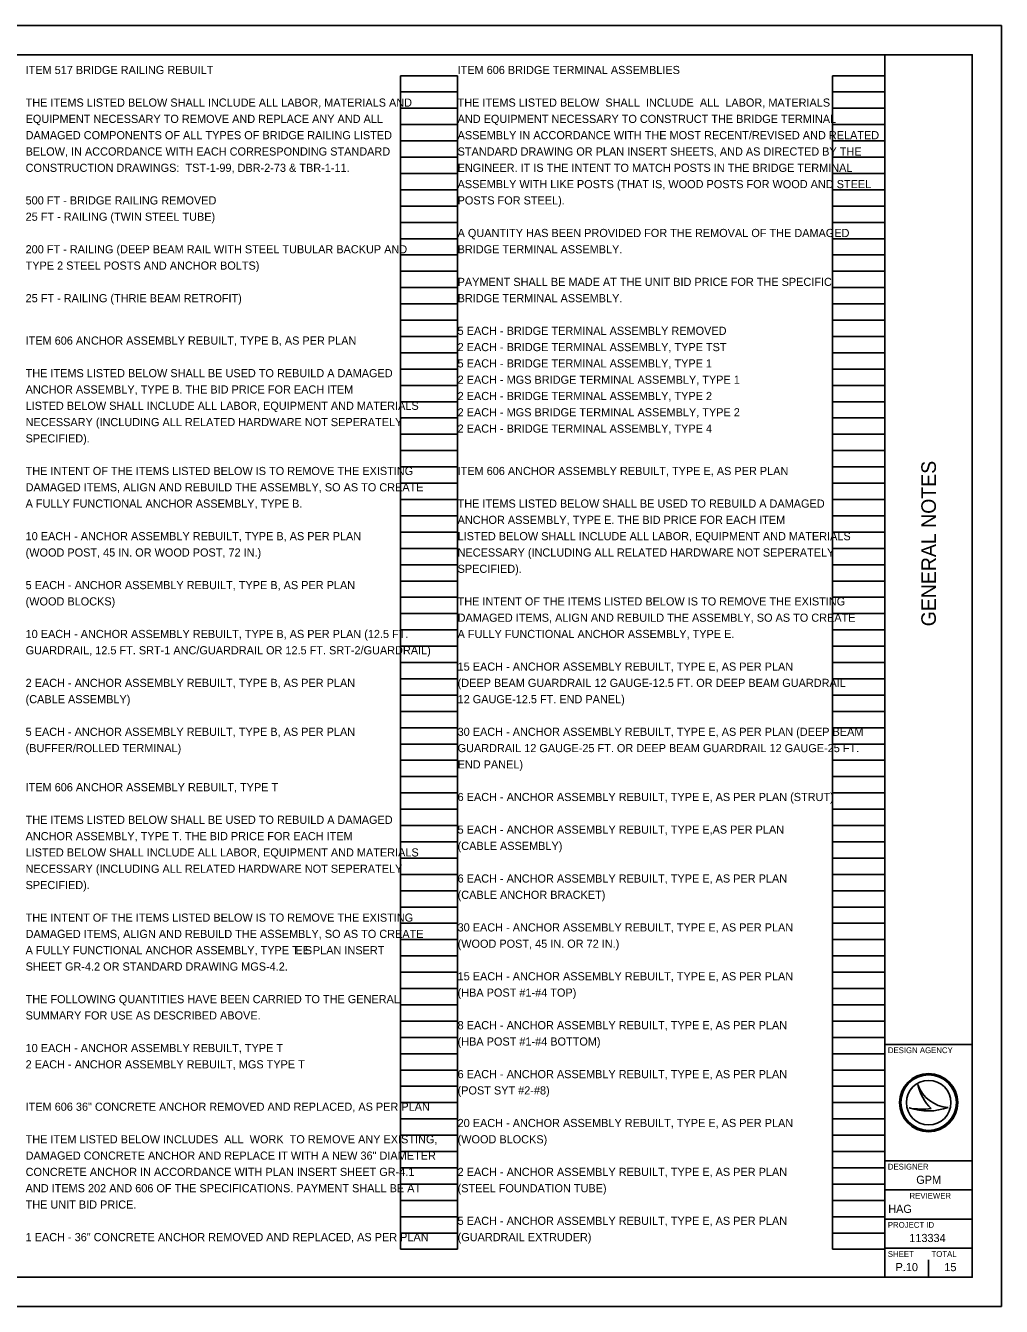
# Model space of a CAD drawing. Extents: x 0 to 34, y 0 to 22.
# Drawn here: x 17.24 to 34, y 0 to 22 of the extents above; entities that cross this region are included whole.
import ezdxf

# ---------------------------------------------------------------- set-up
doc = ezdxf.new("R2010")
doc.units = 0
for name, color, linetype in [('Default', 7, 'Continuous'), ('SH_Border', 7, 'Continuous'), ('SH_Cut_Line', 7, 'Continuous'), ('SH_Data', 7, 'Continuous')]:
    doc.layers.add(name, color=color, linetype=linetype)

msp = doc.modelspace()

# ---------------------------------------------------------------- linework, layer by layer
at = {"layer": 'SH_Border'}
for p, q in [((32, 0.5), (32, 21.5)), ((32, 4.5), (33.5, 4.5)), ((32, 2.5), (33.5, 2.5)), ((32, 2), (33.5, 2)), ((32, 1.5), (33.5, 1.5)), ((32, 1), (33.5, 1))]:
    msp.add_line(p, q, dxfattribs=at)
msp.add_lwpolyline([(1.5, 21.5), (33.5, 21.5), (33.5, 0.5), (1.5, 0.5)], close=True, dxfattribs=at)
at = {"layer": 'SH_Cut_Line'}
msp.add_lwpolyline([(0, 0), (34, 0), (34, 22), (0, 22)], close=True, dxfattribs=at)
at = {"layer": 'SH_Data'}
for p, q in [((23.68, 0.98), (23.68, 21.14)), ((23.68, 21.14), (24.66, 21.14)), ((24.66, 0.98), (24.66, 21.14)), ((31.1, 0.98), (31.1, 21.14)), ((31.1, 21.14), (32, 21.14)), ((32, 0.98), (32, 21.14)), ((23.68, 20.86), (24.66, 20.86)), ((31.1, 20.86), (32, 20.86)), ((23.68, 20.58), (24.66, 20.58)), ((31.1, 20.58), (32, 20.58)), ((23.68, 20.3), (24.66, 20.3)), ((31.1, 20.3), (32, 20.3)), ((23.68, 20.02), (24.66, 20.02)), ((31.1, 20.02), (32, 20.02)), ((23.68, 19.74), (24.66, 19.74)), ((31.1, 19.74), (32, 19.74)), ((23.68, 19.46), (24.66, 19.46)), ((31.1, 19.46), (32, 19.46)), ((23.68, 19.18), (24.66, 19.18)), ((31.1, 19.18), (32, 19.18)), ((23.68, 18.9), (24.66, 18.9)), ((31.1, 18.9), (32, 18.9)), ((23.68, 18.62), (24.66, 18.62)), ((31.1, 18.62), (32, 18.62)), ((23.68, 18.34), (24.66, 18.34)), ((31.1, 18.34), (32, 18.34)), ((23.68, 18.06), (24.66, 18.06)), ((31.1, 18.06), (32, 18.06)), ((23.68, 17.78), (24.66, 17.78)), ((31.1, 17.78), (32, 17.78)), ((23.68, 17.5), (24.66, 17.5)), ((31.1, 17.5), (32, 17.5)), ((23.68, 17.22), (24.66, 17.22)), ((31.1, 17.22), (32, 17.22)), ((23.68, 16.94), (24.66, 16.94)), ((31.1, 16.94), (32, 16.94)), ((23.68, 16.66), (24.66, 16.66)), ((31.1, 16.66), (32, 16.66)), ((23.68, 16.38), (24.66, 16.38)), ((31.1, 16.38), (32, 16.38)), ((23.68, 16.1), (24.66, 16.1)), ((31.1, 16.1), (32, 16.1)), ((23.68, 15.82), (24.66, 15.82)), ((31.1, 15.82), (32, 15.82)), ((23.68, 15.54), (24.66, 15.54)), ((31.1, 15.54), (32, 15.54)), ((23.68, 15.26), (24.66, 15.26)), ((31.1, 15.26), (32, 15.26)), ((23.68, 14.98), (24.66, 14.98)), ((31.1, 14.98), (32, 14.98)), ((23.68, 14.7), (24.66, 14.7)), ((31.1, 14.7), (32, 14.7)), ((23.68, 14.42), (24.66, 14.42)), ((31.1, 14.42), (32, 14.42)), ((23.68, 14.14), (24.66, 14.14)), ((31.1, 14.14), (32, 14.14)), ((23.68, 13.86), (24.66, 13.86)), ((31.1, 13.86), (32, 13.86)), ((23.68, 13.58), (24.66, 13.58)), ((31.1, 13.58), (32, 13.58)), ((23.68, 13.3), (24.66, 13.3)), ((31.1, 13.3), (32, 13.3)), ((23.68, 13.02), (24.66, 13.02)), ((31.1, 13.02), (32, 13.02)), ((23.68, 12.74), (24.66, 12.74)), ((31.1, 12.74), (32, 12.74)), ((23.68, 12.46), (24.66, 12.46)), ((31.1, 12.46), (32, 12.46)), ((23.68, 12.18), (24.66, 12.18)), ((31.1, 12.18), (32, 12.18)), ((23.68, 11.9), (24.66, 11.9)), ((31.1, 11.9), (32, 11.9)), ((23.68, 11.62), (24.66, 11.62)), ((31.1, 11.62), (32, 11.62)), ((23.68, 11.34), (24.66, 11.34)), ((31.1, 11.34), (32, 11.34)), ((23.68, 11.06), (24.66, 11.06)), ((31.1, 11.06), (32, 11.06)), ((23.68, 10.78), (24.66, 10.78)), ((31.1, 10.78), (32, 10.78)), ((23.68, 10.5), (24.66, 10.5)), ((31.1, 10.5), (32, 10.5)), ((23.68, 10.22), (24.66, 10.22)), ((31.1, 10.22), (32, 10.22)), ((23.68, 9.94), (24.66, 9.94)), ((31.1, 9.94), (32, 9.94)), ((23.68, 9.66), (24.66, 9.66)), ((31.1, 9.66), (32, 9.66)), ((23.68, 9.38), (24.66, 9.38)), ((31.1, 9.38), (32, 9.38)), ((23.68, 9.1), (24.66, 9.1)), ((31.1, 9.1), (32, 9.1)), ((23.68, 8.82), (24.66, 8.82)), ((31.1, 8.82), (32, 8.82)), ((23.68, 8.54), (24.66, 8.54)), ((31.1, 8.54), (32, 8.54)), ((23.68, 8.26), (24.66, 8.26)), ((31.1, 8.26), (32, 8.26)), ((23.68, 7.98), (24.66, 7.98)), ((31.1, 7.98), (32, 7.98)), ((23.68, 7.7), (24.66, 7.7)), ((31.1, 7.7), (32, 7.7)), ((23.68, 7.42), (24.66, 7.42)), ((31.1, 7.42), (32, 7.42)), ((23.68, 7.14), (24.66, 7.14)), ((31.1, 7.14), (32, 7.14)), ((23.68, 6.86), (24.66, 6.86)), ((31.1, 6.86), (32, 6.86)), ((23.68, 6.58), (24.66, 6.58)), ((31.1, 6.58), (32, 6.58)), ((23.68, 6.3), (24.66, 6.3)), ((31.1, 6.3), (32, 6.3)), ((23.68, 6.02), (24.66, 6.02)), ((31.1, 6.02), (32, 6.02)), ((23.68, 5.74), (24.66, 5.74)), ((31.1, 5.74), (32, 5.74)), ((23.68, 5.46), (24.66, 5.46)), ((31.1, 5.46), (32, 5.46)), ((23.68, 5.18), (24.66, 5.18)), ((31.1, 5.18), (32, 5.18)), ((23.68, 4.9), (24.66, 4.9)), ((31.1, 4.9), (32, 4.9)), ((23.68, 4.62), (24.66, 4.62)), ((31.1, 4.62), (32, 4.62)), ((23.68, 4.34), (24.66, 4.34)), ((31.1, 4.34), (32, 4.34)), ((23.68, 4.06), (24.66, 4.06)), ((31.1, 4.06), (32, 4.06)), ((23.68, 3.78), (24.66, 3.78)), ((31.1, 3.78), (32, 3.78)), ((32.567, 3.81), (32.567, 3.81)), ((23.68, 3.5), (24.66, 3.5)), ((31.1, 3.5), (32, 3.5)), ((32.417, 3.41), (32.417, 3.41)), ((32.75, 3.5), (32.75, 3.5)), ((33.087, 3.419), (33.087, 3.419)), ((23.68, 3.22), (24.66, 3.22)), ((31.1, 3.22), (32, 3.22)), ((23.68, 2.94), (24.66, 2.94)), ((31.1, 2.94), (32, 2.94)), ((23.68, 2.66), (24.66, 2.66)), ((31.1, 2.66), (32, 2.66)), ((23.68, 2.38), (24.66, 2.38)), ((31.1, 2.38), (32, 2.38)), ((23.68, 2.1), (24.66, 2.1)), ((31.1, 2.1), (32, 2.1)), ((23.68, 1.82), (24.66, 1.82)), ((31.1, 1.82), (32, 1.82)), ((23.68, 1.54), (24.66, 1.54)), ((31.1, 1.54), (32, 1.54)), ((23.68, 1.26), (24.66, 1.26)), ((31.1, 1.26), (32, 1.26)), ((23.68, 0.98), (24.66, 0.98)), ((31.1, 0.98), (32, 0.98)), ((32.375, 0.675), (32.375, 0.675)), ((32.75, 0.5), (32.75, 0.8))]:
    msp.add_line(p, q, dxfattribs=at)
for radius in [0.5, 0.477, 0.477, 0.382]:
    msp.add_circle((32.75, 3.5), radius, dxfattribs=at)
for centre, radius, start, end in [((33.116, 3.998), 0.58, 198.9257, 198.9319), ((33.347, 3.97), 0.796, 191.6379, 191.6421), ((33.116, 3.998), 0.58, 198.9319, 267.1657), ((33.347, 3.97), 0.796, 191.6421, 226.0947), ((32.739, 4.37), 1.013, 251.4576, 290.0832), ((32.648, 4.654), 1.266, 259.4964, 259.4995), ((32.739, 4.37), 1.013, 251.4527, 251.4576), ((32.648, 4.654), 1.266, 259.4995, 276.6672)]:
    msp.add_arc(centre, radius, start, end, dxfattribs=at)

# ---------------------------------------------------------------- texts
at = {"layer": 'Default'}
for s, p in [('ITEM 517 BRIDGE RAILING REBUILT', (17.24, 21.168)), ('ITEM 606 BRIDGE TERMINAL ASSEMBLIES', (24.66, 21.168)), ('THE ITEMS LISTED BELOW SHALL INCLUDE ALL LABOR, MATERIALS AND', (17.24, 20.608)), ('THE ITEMS LISTED BELOW  SHALL  INCLUDE  ALL  LABOR, MATERIALS', (24.66, 20.608)), ('EQUIPMENT NECESSARY TO REMOVE AND REPLACE ANY AND ALL', (17.24, 20.328)), ('AND EQUIPMENT NECESSARY TO CONSTRUCT THE BRIDGE TERMINAL', (24.66, 20.328)), ('DAMAGED COMPONENTS OF ALL TYPES OF BRIDGE RAILING LISTED', (17.24, 20.048)), ('ASSEMBLY IN ACCORDANCE WITH THE MOST RECENT/REVISED AND RELATED', (24.66, 20.048)), ('BELOW, IN ACCORDANCE WITH EACH CORRESPONDING STANDARD', (17.24, 19.768)), ('STANDARD DRAWING OR PLAN INSERT SHEETS, AND AS DIRECTED BY THE', (24.66, 19.768)), ('CONSTRUCTION DRAWINGS:  TST-1-99, DBR-2-73 & TBR-1-11.', (17.24, 19.488)), ('ENGINEER. IT IS THE INTENT TO MATCH POSTS IN THE BRIDGE TERMINAL', (24.66, 19.488)), ('ASSEMBLY WITH LIKE POSTS (THAT IS, WOOD POSTS FOR WOOD AND STEEL', (24.66, 19.208)), ('500 FT - BRIDGE RAILING REMOVED', (17.24, 18.928)), ('POSTS FOR STEEL).', (24.66, 18.928)), ('25 FT - RAILING (TWIN STEEL TUBE)', (17.24, 18.648)), ('A QUANTITY HAS BEEN PROVIDED FOR THE REMOVAL OF THE DAMAGED', (24.66, 18.368)), ('200 FT - RAILING (DEEP BEAM RAIL WITH STEEL TUBULAR BACKUP AND ', (17.24, 18.088)), ('BRIDGE TERMINAL ASSEMBLY.', (24.66, 18.088)), ('TYPE 2 STEEL POSTS AND ANCHOR BOLTS)', (17.24, 17.808)), ('PAYMENT SHALL BE MADE AT THE UNIT BID PRICE FOR THE SPECIFIC', (24.66, 17.528)), ('25 FT - RAILING (THRIE BEAM RETROFIT)', (17.24, 17.248)), ('BRIDGE TERMINAL ASSEMBLY.', (24.66, 17.248)), ('5 EACH - BRIDGE TERMINAL ASSEMBLY REMOVED', (24.66, 16.688)), ('ITEM 606 ANCHOR ASSEMBLY REBUILT, TYPE B, AS PER PLAN', (17.24, 16.52)), ('2 EACH - BRIDGE TERMINAL ASSEMBLY, TYPE TST', (24.66, 16.408)), ('THE ITEMS LISTED BELOW SHALL BE USED TO REBUILD A DAMAGED', (17.24, 15.96)), ('5 EACH - BRIDGE TERMINAL ASSEMBLY, TYPE 1', (24.66, 16.128)), ('2 EACH - MGS BRIDGE TERMINAL ASSEMBLY, TYPE 1', (24.66, 15.848)), ('ANCHOR ASSEMBLY, TYPE B. THE BID PRICE FOR EACH ITEM', (17.24, 15.68)), ('2 EACH - BRIDGE TERMINAL ASSEMBLY, TYPE 2', (24.66, 15.568)), ('LISTED BELOW SHALL INCLUDE ALL LABOR, EQUIPMENT AND MATERIALS', (17.24, 15.4)), ('2 EACH - MGS BRIDGE TERMINAL ASSEMBLY, TYPE 2', (24.66, 15.288)), ('NECESSARY (INCLUDING ALL RELATED HARDWARE NOT SEPERATELY', (17.24, 15.12)), ('SPECIFIED).', (17.24, 14.84)), ('2 EACH - BRIDGE TERMINAL ASSEMBLY, TYPE 4', (24.66, 15.008)), ('THE INTENT OF THE ITEMS LISTED BELOW IS TO REMOVE THE EXISTING', (17.24, 14.28)), ('ITEM 606 ANCHOR ASSEMBLY REBUILT, TYPE E, AS PER PLAN', (24.66, 14.28)), ('DAMAGED ITEMS, ALIGN AND REBUILD THE ASSEMBLY, SO AS TO CREATE', (17.24, 14)), ('A FULLY FUNCTIONAL ANCHOR ASSEMBLY, TYPE B. ', (17.24, 13.72)), ('THE ITEMS LISTED BELOW SHALL BE USED TO REBUILD A DAMAGED', (24.66, 13.72)), ('ANCHOR ASSEMBLY, TYPE E. THE BID PRICE FOR EACH ITEM', (24.66, 13.44)), ('10 EACH - ANCHOR ASSEMBLY REBUILT, TYPE B, AS PER PLAN', (17.24, 13.16)), ('LISTED BELOW SHALL INCLUDE ALL LABOR, EQUIPMENT AND MATERIALS', (24.66, 13.16)), ('(WOOD POST, 45 IN. OR WOOD POST, 72 IN.)', (17.24, 12.88)), ('NECESSARY (INCLUDING ALL RELATED HARDWARE NOT SEPERATELY', (24.66, 12.88)), ('SPECIFIED).', (24.66, 12.6)), ('5 EACH - ANCHOR ASSEMBLY REBUILT, TYPE B, AS PER PLAN', (17.24, 12.32)), ('(WOOD BLOCKS)', (17.24, 12.04)), ('THE INTENT OF THE ITEMS LISTED BELOW IS TO REMOVE THE EXISTING', (24.66, 12.04)), ('DAMAGED ITEMS, ALIGN AND REBUILD THE ASSEMBLY, SO AS TO CREATE', (24.66, 11.76)), ('10 EACH - ANCHOR ASSEMBLY REBUILT, TYPE B, AS PER PLAN (12.5 FT.', (17.24, 11.48)), ('A FULLY FUNCTIONAL ANCHOR ASSEMBLY, TYPE E.', (24.66, 11.48)), ('GUARDRAIL, 12.5 FT. SRT-1 ANC/GUARDRAIL OR 12.5 FT. SRT-2/GUARDRAIL)', (17.24, 11.2)), ('15 EACH - ANCHOR ASSEMBLY REBUILT, TYPE E, AS PER PLAN', (24.66, 10.92)), ('2 EACH - ANCHOR ASSEMBLY REBUILT, TYPE B, AS PER PLAN', (17.24, 10.64)), ('(DEEP BEAM GUARDRAIL 12 GAUGE-12.5 FT. OR DEEP BEAM GUARDRAIL', (24.66, 10.64)), ('(CABLE ASSEMBLY)', (17.24, 10.36)), ('12 GAUGE-12.5 FT. END PANEL)', (24.66, 10.36)), ('5 EACH - ANCHOR ASSEMBLY REBUILT, TYPE B, AS PER PLAN', (17.24, 9.8)), ('30 EACH - ANCHOR ASSEMBLY REBUILT, TYPE E, AS PER PLAN (DEEP BEAM', (24.66, 9.8)), ('(BUFFER/ROLLED TERMINAL)', (17.24, 9.52)), ('GUARDRAIL 12 GAUGE-25 FT. OR DEEP BEAM GUARDRAIL 12 GAUGE-25 FT.', (24.66, 9.52)), ('END PANEL)', (24.66, 9.24)), ('ITEM 606 ANCHOR ASSEMBLY REBUILT, TYPE T', (17.24, 8.848)), ('6 EACH - ANCHOR ASSEMBLY REBUILT, TYPE E, AS PER PLAN (STRUT)', (24.66, 8.68)), ('THE ITEMS LISTED BELOW SHALL BE USED TO REBUILD A DAMAGED', (17.24, 8.288)), ('ANCHOR ASSEMBLY, TYPE T. THE BID PRICE FOR EACH ITEM', (17.24, 8.008)), ('5 EACH - ANCHOR ASSEMBLY REBUILT, TYPE E,AS PER PLAN', (24.66, 8.12)), ('(CABLE ASSEMBLY)', (24.66, 7.84)), ('LISTED BELOW SHALL INCLUDE ALL LABOR, EQUIPMENT AND MATERIALS', (17.24, 7.728)), ('NECESSARY (INCLUDING ALL RELATED HARDWARE NOT SEPERATELY', (17.24, 7.448)), ('SPECIFIED).', (17.24, 7.168)), ('6 EACH - ANCHOR ASSEMBLY REBUILT, TYPE E, AS PER PLAN', (24.66, 7.28)), ('(CABLE ANCHOR BRACKET)', (24.66, 7)), ('THE INTENT OF THE ITEMS LISTED BELOW IS TO REMOVE THE EXISTING', (17.24, 6.608)), ('DAMAGED ITEMS, ALIGN AND REBUILD THE ASSEMBLY, SO AS TO CREATE', (17.24, 6.328)), ('30 EACH - ANCHOR ASSEMBLY REBUILT, TYPE E, AS PER PLAN', (24.66, 6.44)), ('A FULLY FUNCTIONAL ANCHOR ASSEMBLY, TYPE T. S', (17.24, 6.048)), ('EE PLAN INSERT', (21.873, 6.048)), ('(WOOD POST, 45 IN. OR 72 IN.)', (24.66, 6.16)), ('SHEET GR-4.2 OR STANDARD DRAWING MGS-4.2.', (17.24, 5.768)), ('15 EACH - ANCHOR ASSEMBLY REBUILT, TYPE E, AS PER PLAN', (24.66, 5.6)), ('THE FOLLOWING QUANTITIES HAVE BEEN CARRIED TO THE GENERAL', (17.24, 5.208)), ('(HBA POST #1-#4 TOP)', (24.66, 5.32)), ('SUMMARY FOR USE AS DESCRIBED ABOVE.  ', (17.24, 4.928)), ('8 EACH - ANCHOR ASSEMBLY REBUILT, TYPE E, AS PER PLAN', (24.66, 4.76)), ('(HBA POST #1-#4 BOTTOM)', (24.66, 4.48)), ('10 EACH - ANCHOR ASSEMBLY REBUILT, TYPE T ', (17.24, 4.368)), ('2 EACH - ANCHOR ASSEMBLY REBUILT, MGS TYPE T', (17.24, 4.088)), ('6 EACH - ANCHOR ASSEMBLY REBUILT, TYPE E, AS PER PLAN', (24.66, 3.92)), ('(POST SYT #2-#8)', (24.66, 3.64)), ('ITEM 606 36" CONCRETE ANCHOR REMOVED AND REPLACED, AS PER PLAN', (17.24, 3.36)), ('20 EACH - ANCHOR ASSEMBLY REBUILT, TYPE E, AS PER PLAN', (24.66, 3.08)), ('THE ITEM LISTED BELOW INCLUDES  ALL  WORK  TO REMOVE ANY EXISTING,', (17.24, 2.8)), ('(WOOD BLOCKS)', (24.66, 2.8)), ('DAMAGED CONCRETE ANCHOR AND REPLACE IT WITH A NEW 36" DIAMETER', (17.24, 2.52)), ('CONCRETE ANCHOR IN ACCORDANCE WITH PLAN INSERT SHEET GR-4.1', (17.24, 2.24)), ('2 EACH - ANCHOR ASSEMBLY REBUILT, TYPE E, AS PER PLAN', (24.66, 2.24)), ('AND ITEMS 202 AND 606 OF THE SPECIFICATIONS. PAYMENT SHALL BE AT', (17.24, 1.96)), ('(STEEL FOUNDATION TUBE)', (24.66, 1.96)), ('THE UNIT BID PRICE.', (17.24, 1.68)), ('5 EACH - ANCHOR ASSEMBLY REBUILT, TYPE E, AS PER PLAN', (24.66, 1.4)), ('1 EACH - 36" CONCRETE ANCHOR REMOVED AND REPLACED, AS PER PLAN', (17.24, 1.12)), ('(GUARDRAIL EXTRUDER)', (24.66, 1.12))]:
    msp.add_text(s, height=0.14, dxfattribs=at).set_placement(p)
at = {"layer": 'SH_Data'}
msp.add_text('GENERAL NOTES', height=0.25, rotation=90, dxfattribs=at).set_placement((32.875, 11.682))
for s, height, p in [('DESIGN AGENCY', 0.1, (32.05, 4.35)), ('DESIGNER', 0.1, (32.05, 2.35)), ('GPM', 0.14, (32.538, 2.105)), ('REVIEWER', 0.1, (32.422, 1.85)), ('HAG', 0.14, (32.057, 1.605)), ('PROJECT ID', 0.1, (32.05, 1.35)), ('113334', 0.14, (32.418, 1.105)), ('SHEET', 0.1, (32.05, 0.85)), ('TOTAL', 0.1, (32.8, 0.85)), ('P.10', 0.14, (32.182, 0.605)), ('15', 0.14, (33.02, 0.605))]:
    msp.add_text(s, height=height, dxfattribs=at).set_placement(p)

doc.saveas('drawing.dxf')
